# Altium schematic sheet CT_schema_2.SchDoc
size 199 x 169 mm
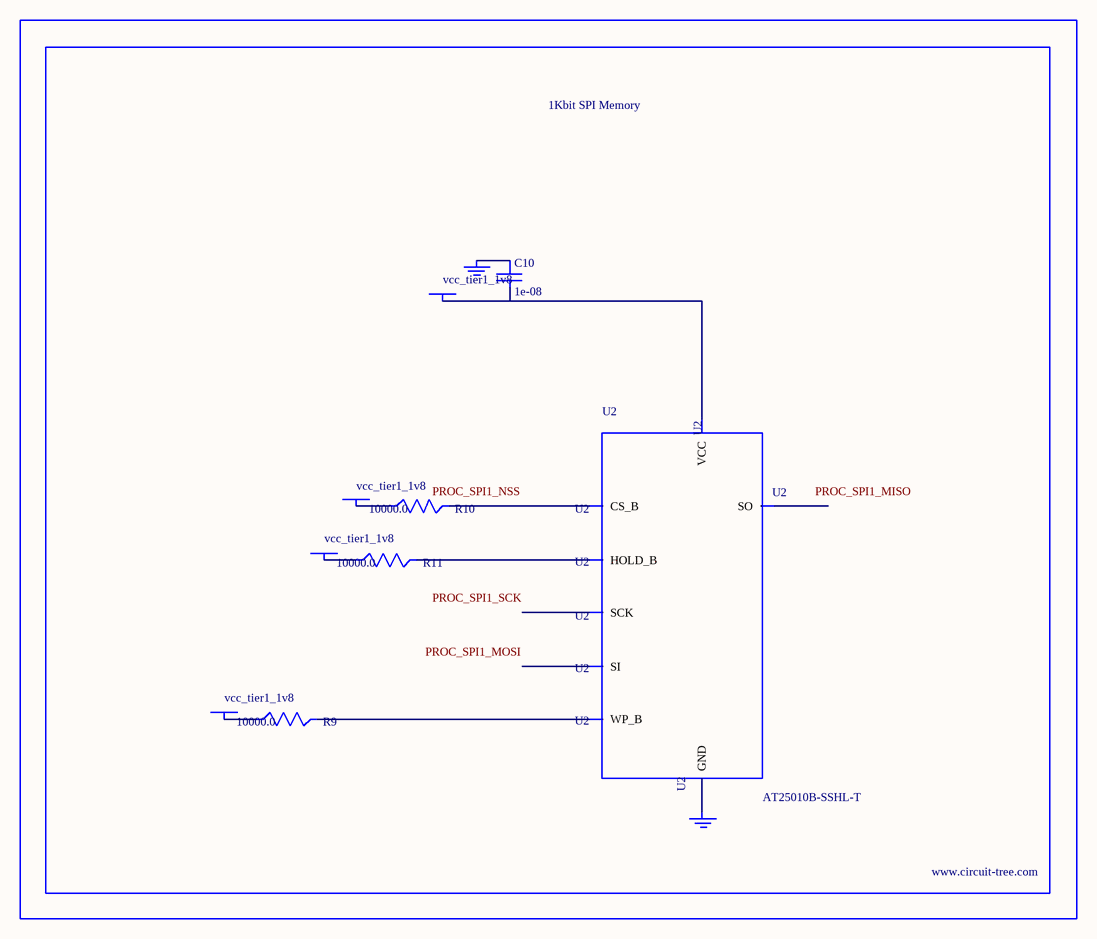
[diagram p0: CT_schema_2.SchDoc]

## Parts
BORDER1  (no value)
C10  1e-08  [C0402]
GND_INSTANCE_1_0  (no value)
GND_INSTANCE_1_1  (no value)
POWER_INSTANCE_1_0  vcc_tier1_1v8
POWER_INSTANCE_1_1  vcc_tier1_1v8
POWER_INSTANCE_1_2  vcc_tier1_1v8
POWER_INSTANCE_1_3  vcc_tier1_1v8
R9  10000.0  [R0603]
R10  10000.0  [R0603]
R11  10000.0  [R0603]
U2  AT25010B-SSHL-T  [SOIC-8]

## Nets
NetC10_1: C10.1 GND_INSTANCE_1_0.0(GND)
NetC10_2: C10.2 POWER_INSTANCE_1_3.0(PWR) U2.8(VCC)
NetGND_INSTANCE_1_1_0: GND_INSTANCE_1_1.0(GND) U2.4(GND)
NetPOWER_INSTANCE_1_0_0: POWER_INSTANCE_1_0.0(PWR) R10.1
NetPOWER_INSTANCE_1_1_0: POWER_INSTANCE_1_1.0(PWR) R9.1
NetPOWER_INSTANCE_1_2_0: POWER_INSTANCE_1_2.0(PWR) R11.1
NetR9_2: R9.2 U2.3(WP_B)
NetR10_2: R10.2 U2.1(CS_B)
NetR11_2: R11.2 U2.7(HOLD_B)

Not connected (* = marked no-connect by the designer): U2 2(SO) 5(SI) 6(SCK)

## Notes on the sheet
- Labels drawn without touching a wire or pin: PROC_SPI1_MISO, PROC_SPI1_MOSI, PROC_SPI1_NSS, PROC_SPI1_SCK

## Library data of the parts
BORDER1 = BORDER_PAGE1
C10 = C0402C103K3RAC
GND_INSTANCE_1_0 GND_INSTANCE_1_1 = GND
POWER_INSTANCE_1_0-POWER_INSTANCE_1_3 = PWR
R9-R11 = RC0603JR-0710KL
